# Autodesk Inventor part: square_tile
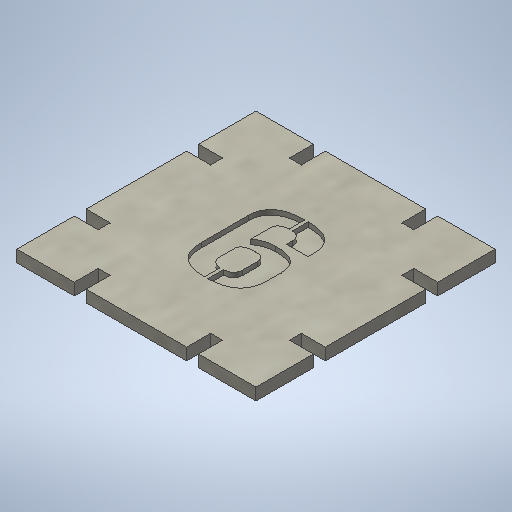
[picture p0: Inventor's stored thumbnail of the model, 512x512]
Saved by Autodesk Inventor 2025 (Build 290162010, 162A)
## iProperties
Created: 2025-02
Part Number: square_tile
Material: Paper
Document SubType Name: Modeling
Designer: BennF
Density: 0.93 g/cm^3
Appearance: Cardboard - Chipboard
Author: BennF
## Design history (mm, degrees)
sketch "Sketch2"
  geometry: L1 (-25, -25)-(-25, -13); L2 (-25, -13)-(-20, -13); L3 (-20, -13)-(-20, -10.5); L4 (-20, -10.5)-(-25, -10.5); L5 (-25, -10.5)-(-25, 10.5); L6 (-25, 10.5)-(-20, 10.5); L7 (-20, 10.5)-(-20, 13); L8 (-20, 13)-(-25, 13); L9 (-25, 13)-(-25, 25); L10 (25, 25)-(25, 13); L11 (25, 13)-(20, 13); L12 (20, 13)-(20, 10.5); L13 (20, 10.5)-(25, 10.5); L14 (25, -10.5)-(20, -10.5); L15 (20, -13)-(20, -10.5); L16 (25, -10.5)-(25, 10.5); L17 (20, -13)-(25, -13); L18 (25, -13)-(25, -25); L19 (0, 25)-(0, -25); L20 (-25, 0)-(25, 0); L21 (-25, -25)-(-13, -25); L22 (-13, -25)-(-13, -20); L23 (-13, -20)-(-10.5, -20); L24 (-10.5, -20)-(-10.5, -25); L25 (-10.5, -25)-(10.5, -25); L26 (10.5, -25)-(10.5, -20); L27 (10.5, -20)-(13, -20); L28 (13, -20)-(13, -25); L29 (13, -25)-(25, -25); L30 (-25, 25)-(-13, 25); L31 (-13, 25)-(-13, 20); L32 (-13, 20)-(-10.5, 20); L33 (-10.5, 20)-(-10.5, 25); L34 (-10.5, 25)-(10.5, 25); L35 (10.5, 25)-(10.5, 20); L36 (10.5, 20)-(13, 20); L37 (13, 20)-(13, 25); L38 (13, 25)-(25, 25); 1 further point
  constraints: 76 end point, 30 point on line, 18 perpendicular, 13 equal length, 4 midpoint, 3 vertical, 2 horizontal, 1 horizontal alignment, 1 parallel, 1 vertical alignment
  dimensions: "d0" = 50 distance between parallel lines of L16 L5 (= squ_side); "d1" = 12 distance of L8.end L9.end (= slot_dis_2); "d2" = 5 distance of L7.end L8.end (= slot_depth); "d3" = 2.5 distance of L6.end L7.end (= thickness)
extrude "Extrusion1" new body sketch "Sketch2" distance "d4" = 2.5 (= thickness); taper "d5" = 0 deg
sketch "Sketch4"
  geometry: L1 (-5, 5)-(5, 5); L2 (5, 5)-(5, -5); L3 (5, -5)-(-5, -5); L4 (-5, -5)-(-5, 5); L5 (-10.5, -25)-(10.5, -25) reference; 3 further points
  constraints: 2 midpoint, 1 horizontal alignment, 1 parallel, 1 perpendicular, 1 vertical alignment, 2 other
  dimensions: "d6" = 10 distance of L1.start L1.end
emboss "Emboss1" sketch "Sketch4" dims "d7" = 1, "d8" = 0
sketch "laser"
  geometry: L1 (0.525, 7.078)-(0.525, 10.422) reference; L2 (6.827, 5.141)-(6.827, 4.061) reference; L3 (6.827, 4.061)-(2.315, 4.061) reference; L4 (2.315, 4.061)-(2.315, 5.392) reference; L5 (-2.359, -1.723)-(-2.359, -5.185) reference; L6 (-0.362, -7.123)-(-0.362, -10.407) reference; L7 (-6.901, -4.578)-(-6.901, 5.274) reference; L8 (-0.185, 10.422)-(-0.185, 7.108) reference; L9 (-2.359, 5.274)-(-2.359, 1.25) reference; L10 (6.93, -1.679)-(6.93, -4.682) reference; L11 (0.318, -10.407)-(0.318, -7.123) reference; L12 (2.389, -5.111)-(2.389, -2.004) reference; L13 (20, -10.5)-(25, -10.5) reference; L14 (25, -10.5)-(25, 10.5) reference; L15 (25, 10.5)-(20, 10.5) reference; L16 (20, 10.5)-(20, 13) reference; L17 (20, 13)-(25, 13) reference; L18 (25, 13)-(25, 25) reference; L19 (25, 25)-(13, 25) reference; L20 (13, 25)-(13, 20) reference; L21 (13, 20)-(10.5, 20) reference; L22 (10.5, 20)-(10.5, 25) reference; L23 (10.5, 25)-(-10.5, 25) reference; L24 (-10.5, 25)-(-10.5, 20) reference; L25 (-10.5, 20)-(-13, 20) reference; L26 (-13, 20)-(-13, 25) reference; L27 (-13, 25)-(-25, 25) reference; L28 (-25, 25)-(-25, 13) reference; L29 (-25, 13)-(-20, 13) reference; L30 (-20, 13)-(-20, 10.5) reference; L31 (-20, 10.5)-(-25, 10.5) reference; L32 (-25, 10.5)-(-25, -10.5) reference; L33 (-25, -10.5)-(-20, -10.5) reference; L34 (-20, -10.5)-(-20, -13) reference; L35 (-20, -13)-(-25, -13) reference; L36 (-25, -13)-(-25, -25) reference; L37 (-25, -25)-(-13, -25) reference; L38 (-13, -25)-(-13, -20) reference; L39 (-13, -20)-(-10.5, -20) reference; L40 (-10.5, -20)-(-10.5, -25) reference; L41 (-10.5, -25)-(10.5, -25) reference; L42 (10.5, -25)-(10.5, -20) reference; L43 (10.5, -20)-(13, -20) reference; L44 (13, -20)-(13, -25) reference; L45 (13, -25)-(25, -25) reference; L46 (25, -25)-(25, -13) reference; L47 (25, -13)-(20, -13) reference; L48 (20, -13)-(20, -10.5) reference; 3 further points
  constraints: 12 other
  node "Projected Loop7"
body "Solid1"
other parameters: "thickness" = 2.5 [user parameter; used in 2 equation terms], "squ_side" = 50 [user parameter; used in 1 equation term], "clearence" = -0.5 [user parameter], "slot_depth" = 5 [user parameter; used in 1 equation term], "slot_dis_1" = 5 [user parameter], "slot_dis_2" = 12 [user parameter; used in 1 equation term], "slot_clearenece" = 3 [user parameter], "con_angle_1" = 20.34444 [user parameter], "con_angle_2" = 60 deg [user parameter], "con_angle_3" = 12.30959 [user parameter], "con_angle_4" = 19.10633 [user parameter], "con_angle_5" = 24.11865 [user parameter]
